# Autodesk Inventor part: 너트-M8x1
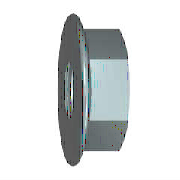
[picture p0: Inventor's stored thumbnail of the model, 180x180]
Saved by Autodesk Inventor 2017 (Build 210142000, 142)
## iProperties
Created: 2015-12
Part Number: 너트-M8x1
Material: 스테인리스강
Description: 플랜지붙이 6각 너트 - 일반 스레드
Document SubType Name: Modeling
Standard: ISO 4161
Designer: mdu
Standard Revision: 2판 1999-03-15
Standards Organization: ISO
Language: ko-KR
Size Designation: M8
Categories: <MemberInstance><Categories><Category DisplayName="조임쇠" InternalName="e4da775c-781d-43d5-af7c-5136215cf5a6" Mnemonic="FSTN"><Category DisplayName="너트" InternalN
Density: 8.08 g/cm^3
Mass: 9.03298 g
Surface Area: 8.90186 cm^2
Volume: 1.11794 cm^3
Appearance: 강철
Author: mdu
IsCustomPart: 1
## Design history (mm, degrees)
sketch "스케치1"
  geometry: L1 (-1.844, 0)-(9.641, 0) reference; L2 (3.107, 6.5)-(2.288, 8.257); L3 (3.107, 6.5)-(8, 6.5); L4 (8, 6.5)-(8, 0); L5 (3.107, 6.5)-(3.107, 0); L6 (0, -1.835)-(0, 11.01) reference; A1 r 1.2 centre (1.2, 7.75) between (2.288, 8.257) and (0, 7.75); 1 further point
  constraints: 8 end point, 3 point on line, 2 perpendicular, 2 point on circle, 2 tangent, 1 centre point, 1 parallel
  dimensions: "d2" = 13 diameter of L3 L1 (= SW); "d4" = 17.9 dimension on A1 L1 (= LADI); "d5" = 1.2 radius of A1 (= PHH); "d15" = 8 distance between parallel lines of L4 L6 (= KOH); "d16" = 25 deg angle of L6 L2 (= KEWI)
revolve "링" sketch "스케치1" stored, may be unused: angle "d8" = 90 deg
sketch "스케치2"
  geometry: L1 (-6.5, -3.753)-(-6.5, 3.753); L2 (-6.5, 3.753)-(0, 7.506); L3 (0, 7.506)-(6.5, 3.753); L4 (6.5, 3.753)-(6.5, -3.753); L5 (6.5, -3.753)-(0, -7.506); L6 (0, -7.506)-(-6.5, -3.753); C1 r 4.9 at (0, 0); C2 r 7.75 at (0, 0) reference; 1 further point
  constraints: 12 end point, 1 centre point, 1 coincident, 1 vertical, 11 other
  dimensions: "d6" = 15.01111 distance of L5.end L2.end (= 1.1547 x SW)
extrude "본체" join sketch "스케치2" distance "d7" = 8 (= KOH); taper "d9" = 0 deg
sketch "스케치3"
  geometry: L1 (2.638, 7.506)-(8, 7.506) reference; L2 (8, 3.753)-(8, 7.506) reference; L3 (0, -7.75)-(0, 7.75) reference; L4 (-1.6, 0)-(9.6, 0) reference; L5 (7.419, 7.506)-(8, 6.5)
  constraints: 2 end point, 2 point on line
  dimensions: "d10" = 30 deg angle of L2 L5 (= ANG1); "d11" = 13 diameter of L5.end L4 (= SW0)
revolve "모따기1" sketch "스케치3" stored, may be unused: angle "d24" = 90 deg
sketch "스케치4"
  geometry: C1 r 7.75 at (0, 0) reference; 1 further point
  constraints: 1 coincident
hole "스레드" sketch "스케치4" at (0, 0) diameter "d25" = 6.647; stored, may be unused: countersink angle "d29" = 82 deg, drill point angle "d31" = 118 deg; dims "d26" = 6, "d27" = 4, "d28" = 2, "d30" = 8
workaxis "Work Axis1"
workplane "Work Plane1"
body "Solid1"
chamfer "모따기2" distance "d12" = 0.67658 (= -0.5 x GD1 + 0.5 x NND); stored, may be unused: angle "d13" = 30 deg, second distance "d46" = 0.67658 (= -0.5 x GD1 + 0.5 x NND)
chamfer "모따기3" distance "d51" = 0.67658 (= -0.5 x GD1 + 0.5 x NND); stored, may be unused: second distance "d52" = 2, angle "d53" = 45 deg
other parameters: "ANG1" = 30 deg [user parameter; used in 1 equation term], "KEWI" = 25 deg [user parameter; used in 1 equation term], "NND" = 8 [user parameter; used in 4 equation terms], "LADI" = 17.9 [user parameter; used in 2 equation terms], "SW" = 13 [user parameter; used in 3 equation terms], "PHH" = 1.2 [user parameter; used in 3 equation terms], "KOH" = 8 (= NND) [user parameter; used in 2 equation terms], "SW0" = 13 [user parameter; used in 1 equation term], "GD1" = 6.64684 (computed from THREADDIA, PTC, TOA) [user parameter; used in 3 equation terms], "d1" = 17.9 (= LADI), "d3" = 1.2 (= PHH), "d45" = 0, "d47" = 0, "d49" = 0, "d54" = 0, "GUL" = 0.67658 (= 0.541266 x PTC) [user parameter], "TPU" = 8 (computed from PTC) [user parameter], "RR" = 1.2 (= PHH) [user parameter], "THREADDIA" = 8 [user parameter; used in 1 equation term], "TOA" = 30 deg [user parameter; used in 1 equation term], "PTC" = 1.25 [user parameter; used in 4 equation terms], "GAL" = 0.67658 (= 0.541266 x PTC) [user parameter], "E0" = 15.015 (= 1.155 x SW) [user parameter]
